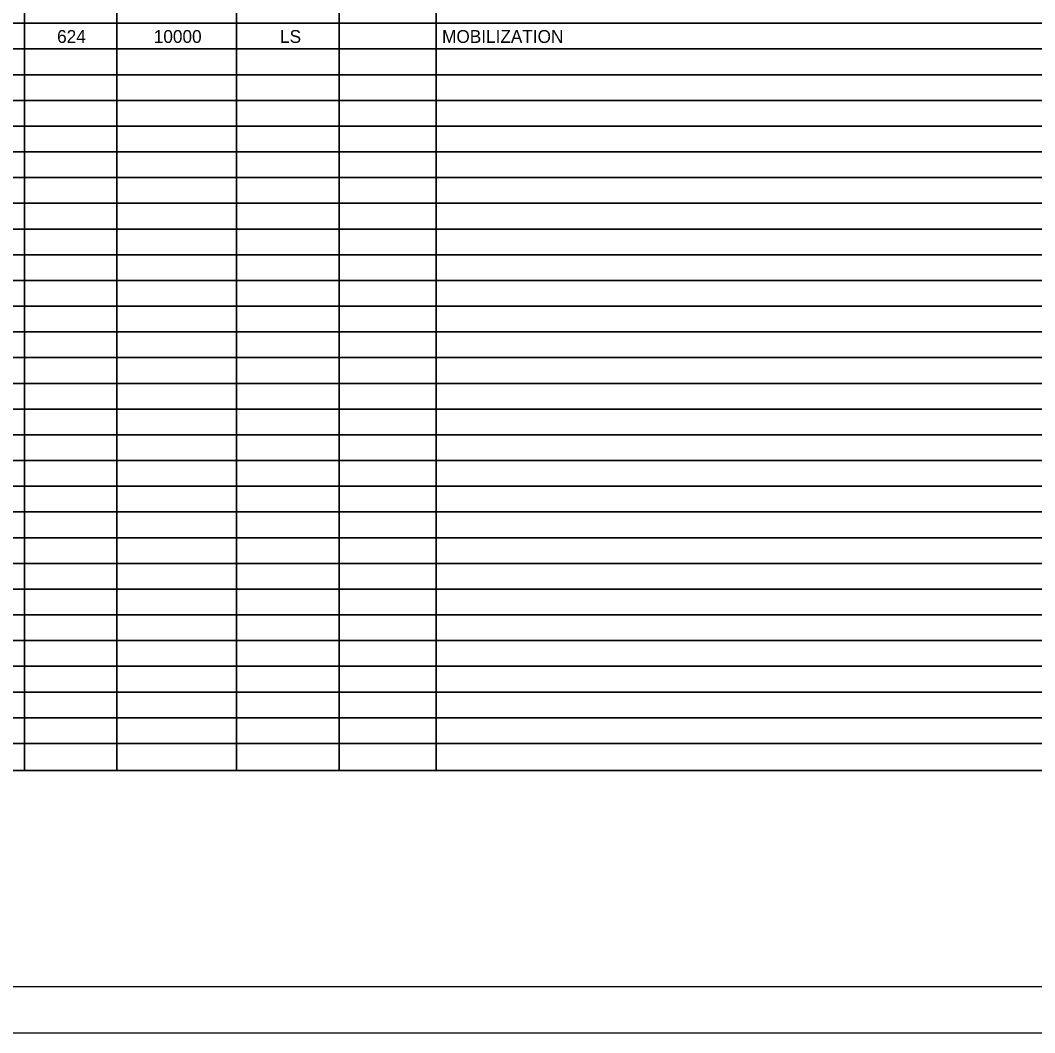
# Model space of a CAD drawing. Extents: x 0 to 34, y 0 to 22.
# Drawn here: x 11.97 to 23.01, y 0 to 11.02 of the extents above; entities that cross this region are included whole.
import ezdxf

# ---------------------------------------------------------------- set-up
doc = ezdxf.new("R2010")
doc.units = 0
for name, color, linetype in [('SH_Border', 7, 'Continuous'), ('SH_Cut_Line', 7, 'Continuous'), ('SH_Data', 7, 'Continuous'), ('SH_Text', 7, 'Continuous')]:
    doc.layers.add(name, color=color, linetype=linetype)

msp = doc.modelspace()

# ---------------------------------------------------------------- linework, layer by layer
at = {"layer": 'SH_Border'}
msp.add_lwpolyline([(1.5, 21.5), (33.5, 21.5), (33.5, 0.5), (1.5, 0.5)], close=True, dxfattribs=at)
at = {"layer": 'SH_Cut_Line'}
msp.add_lwpolyline([(0, 0), (34, 0), (34, 22), (0, 22)], close=True, dxfattribs=at)
at = {"layer": 'SH_Data'}
for p, q in [((16.492, 18.5), (16.492, 2.853)), ((12.012, 14.909), (12.012, 2.853)), ((13.016, 14.909), (13.016, 2.853)), ((14.318, 14.909), (14.318, 2.853)), ((15.438, 14.909), (15.438, 2.853)), ((6, 10.989), (27.049, 10.989)), ((6, 10.709), (27.049, 10.709)), ((6, 10.429), (27.049, 10.429)), ((6, 10.149), (27.049, 10.149)), ((6, 9.869), (27.049, 9.869)), ((6, 9.589), (27.049, 9.589)), ((6, 9.309), (27.049, 9.309)), ((6, 9.029), (27.049, 9.029)), ((6, 8.749), (27.049, 8.749)), ((6, 8.469), (27.049, 8.469)), ((6, 8.189), (27.049, 8.189)), ((6, 7.909), (27.049, 7.909)), ((6, 7.629), (27.049, 7.629)), ((6, 7.349), (27.049, 7.349)), ((6, 7.069), (27.049, 7.069)), ((6, 6.789), (27.049, 6.789)), ((6, 6.509), (27.049, 6.509)), ((6, 6.229), (27.049, 6.229)), ((6, 5.949), (27.049, 5.949)), ((6, 5.669), (27.049, 5.669)), ((6, 5.389), (27.049, 5.389)), ((6, 5.109), (27.049, 5.109)), ((6, 4.829), (27.049, 4.829)), ((6, 4.549), (27.049, 4.549)), ((6, 4.269), (27.049, 4.269)), ((6, 3.989), (27.049, 3.989)), ((6, 3.709), (27.049, 3.709)), ((6, 3.429), (27.049, 3.429)), ((6, 3.149), (27.049, 3.149)), ((6, 2.853), (27.049, 2.853))]:
    msp.add_line(p, q, dxfattribs=at)
at = {"layer": 'SH_Text'}
for points in [[(10.216, 11.269), (12.012, 11.269), (12.012, 10.989), (10.216, 10.989)], [(12.012, 11.269), (13.016, 11.269), (13.016, 10.989), (12.012, 10.989)], [(13.016, 11.269), (14.318, 11.269), (14.318, 10.989), (13.016, 10.989)], [(14.318, 11.269), (15.438, 11.269), (15.438, 10.989), (14.318, 10.989)], [(15.438, 11.269), (16.492, 11.269), (16.492, 10.989), (15.438, 10.989)], [(16.492, 11.269), (25.765, 11.269), (25.765, 10.989), (16.492, 10.989)], [(10.216, 10.989), (12.012, 10.989), (12.012, 10.709), (10.216, 10.709)], [(12.012, 10.989), (13.016, 10.989), (13.016, 10.709), (12.012, 10.709)], [(13.016, 10.989), (14.318, 10.989), (14.318, 10.709), (13.016, 10.709)], [(14.318, 10.989), (15.438, 10.989), (15.438, 10.709), (14.318, 10.709)], [(15.438, 10.989), (16.492, 10.989), (16.492, 10.709), (15.438, 10.709)], [(16.492, 10.989), (25.765, 10.989), (25.765, 10.709), (16.492, 10.709)], [(10.216, 10.709), (12.012, 10.709), (12.012, 10.429), (10.216, 10.429)], [(12.012, 10.709), (13.016, 10.709), (13.016, 10.429), (12.012, 10.429)], [(13.016, 10.709), (14.318, 10.709), (14.318, 10.429), (13.016, 10.429)], [(14.318, 10.709), (15.438, 10.709), (15.438, 10.429), (14.318, 10.429)], [(15.438, 10.709), (16.492, 10.709), (16.492, 10.429), (15.438, 10.429)], [(16.492, 10.709), (25.765, 10.709), (25.765, 10.429), (16.492, 10.429)], [(10.216, 10.429), (12.012, 10.429), (12.012, 10.149), (10.216, 10.149)], [(12.012, 10.429), (13.016, 10.429), (13.016, 10.149), (12.012, 10.149)], [(13.016, 10.429), (14.318, 10.429), (14.318, 10.149), (13.016, 10.149)], [(14.318, 10.429), (15.438, 10.429), (15.438, 10.149), (14.318, 10.149)], [(15.438, 10.429), (16.492, 10.429), (16.492, 10.149), (15.438, 10.149)], [(16.492, 10.429), (25.765, 10.429), (25.765, 10.149), (16.492, 10.149)], [(10.216, 10.149), (12.012, 10.149), (12.012, 9.869), (10.216, 9.869)], [(12.012, 10.149), (13.016, 10.149), (13.016, 9.869), (12.012, 9.869)], [(13.016, 10.149), (14.318, 10.149), (14.318, 9.869), (13.016, 9.869)], [(14.318, 10.149), (15.438, 10.149), (15.438, 9.869), (14.318, 9.869)], [(15.438, 10.149), (16.492, 10.149), (16.492, 9.869), (15.438, 9.869)], [(16.492, 10.149), (25.765, 10.149), (25.765, 9.869), (16.492, 9.869)], [(10.216, 9.869), (12.012, 9.869), (12.012, 9.589), (10.216, 9.589)], [(12.012, 9.869), (13.016, 9.869), (13.016, 9.589), (12.012, 9.589)], [(13.016, 9.869), (14.318, 9.869), (14.318, 9.589), (13.016, 9.589)], [(14.318, 9.869), (15.438, 9.869), (15.438, 9.589), (14.318, 9.589)], [(15.438, 9.869), (16.492, 9.869), (16.492, 9.589), (15.438, 9.589)], [(16.492, 9.869), (25.765, 9.869), (25.765, 9.589), (16.492, 9.589)], [(10.216, 9.589), (12.012, 9.589), (12.012, 9.309), (10.216, 9.309)], [(12.012, 9.589), (13.016, 9.589), (13.016, 9.309), (12.012, 9.309)], [(13.016, 9.589), (14.318, 9.589), (14.318, 9.309), (13.016, 9.309)], [(14.318, 9.589), (15.438, 9.589), (15.438, 9.309), (14.318, 9.309)], [(15.438, 9.589), (16.492, 9.589), (16.492, 9.309), (15.438, 9.309)], [(16.492, 9.589), (25.765, 9.589), (25.765, 9.309), (16.492, 9.309)], [(10.216, 9.309), (12.012, 9.309), (12.012, 9.029), (10.216, 9.029)], [(12.012, 9.309), (13.016, 9.309), (13.016, 9.029), (12.012, 9.029)], [(13.016, 9.309), (14.318, 9.309), (14.318, 9.029), (13.016, 9.029)], [(14.318, 9.309), (15.438, 9.309), (15.438, 9.029), (14.318, 9.029)], [(15.438, 9.309), (16.492, 9.309), (16.492, 9.029), (15.438, 9.029)], [(16.492, 9.309), (25.765, 9.309), (25.765, 9.029), (16.492, 9.029)], [(10.216, 9.029), (12.012, 9.029), (12.012, 8.749), (10.216, 8.749)], [(12.012, 9.029), (13.016, 9.029), (13.016, 8.749), (12.012, 8.749)], [(13.016, 9.029), (14.318, 9.029), (14.318, 8.749), (13.016, 8.749)], [(14.318, 9.029), (15.438, 9.029), (15.438, 8.749), (14.318, 8.749)], [(15.438, 9.029), (16.492, 9.029), (16.492, 8.749), (15.438, 8.749)], [(16.492, 9.029), (25.765, 9.029), (25.765, 8.749), (16.492, 8.749)], [(10.216, 8.749), (12.012, 8.749), (12.012, 8.469), (10.216, 8.469)], [(12.012, 8.749), (13.016, 8.749), (13.016, 8.469), (12.012, 8.469)], [(13.016, 8.749), (14.318, 8.749), (14.318, 8.469), (13.016, 8.469)], [(14.318, 8.749), (15.438, 8.749), (15.438, 8.469), (14.318, 8.469)], [(15.438, 8.749), (16.492, 8.749), (16.492, 8.469), (15.438, 8.469)], [(16.492, 8.749), (25.765, 8.749), (25.765, 8.469), (16.492, 8.469)], [(10.216, 8.469), (12.012, 8.469), (12.012, 8.189), (10.216, 8.189)], [(12.012, 8.469), (13.016, 8.469), (13.016, 8.189), (12.012, 8.189)], [(13.016, 8.469), (14.318, 8.469), (14.318, 8.189), (13.016, 8.189)], [(14.318, 8.469), (15.438, 8.469), (15.438, 8.189), (14.318, 8.189)], [(15.438, 8.469), (16.492, 8.469), (16.492, 8.189), (15.438, 8.189)], [(16.492, 8.469), (25.765, 8.469), (25.765, 8.189), (16.492, 8.189)], [(10.216, 8.189), (12.012, 8.189), (12.012, 7.909), (10.216, 7.909)], [(12.012, 8.189), (13.016, 8.189), (13.016, 7.909), (12.012, 7.909)], [(13.016, 8.189), (14.318, 8.189), (14.318, 7.909), (13.016, 7.909)], [(14.318, 8.189), (15.438, 8.189), (15.438, 7.909), (14.318, 7.909)], [(15.438, 8.189), (16.492, 8.189), (16.492, 7.909), (15.438, 7.909)], [(16.492, 8.189), (25.765, 8.189), (25.765, 7.909), (16.492, 7.909)], [(10.216, 7.909), (12.012, 7.909), (12.012, 7.629), (10.216, 7.629)], [(12.012, 7.909), (13.016, 7.909), (13.016, 7.629), (12.012, 7.629)], [(13.016, 7.909), (14.318, 7.909), (14.318, 7.629), (13.016, 7.629)], [(14.318, 7.909), (15.438, 7.909), (15.438, 7.629), (14.318, 7.629)], [(15.438, 7.909), (16.492, 7.909), (16.492, 7.629), (15.438, 7.629)], [(16.492, 7.909), (25.765, 7.909), (25.765, 7.629), (16.492, 7.629)], [(10.216, 7.629), (12.012, 7.629), (12.012, 7.349), (10.216, 7.349)], [(12.012, 7.629), (13.016, 7.629), (13.016, 7.349), (12.012, 7.349)], [(13.016, 7.629), (14.318, 7.629), (14.318, 7.349), (13.016, 7.349)], [(14.318, 7.629), (15.438, 7.629), (15.438, 7.349), (14.318, 7.349)], [(15.438, 7.629), (16.492, 7.629), (16.492, 7.349), (15.438, 7.349)], [(16.492, 7.629), (25.765, 7.629), (25.765, 7.349), (16.492, 7.349)], [(10.216, 7.349), (12.012, 7.349), (12.012, 7.069), (10.216, 7.069)], [(12.012, 7.349), (13.016, 7.349), (13.016, 7.069), (12.012, 7.069)], [(13.016, 7.349), (14.318, 7.349), (14.318, 7.069), (13.016, 7.069)], [(14.318, 7.349), (15.438, 7.349), (15.438, 7.069), (14.318, 7.069)], [(15.438, 7.349), (16.492, 7.349), (16.492, 7.069), (15.438, 7.069)], [(16.492, 7.349), (25.765, 7.349), (25.765, 7.069), (16.492, 7.069)], [(10.216, 7.069), (12.012, 7.069), (12.012, 6.789), (10.216, 6.789)], [(12.012, 7.069), (13.016, 7.069), (13.016, 6.789), (12.012, 6.789)], [(13.016, 7.069), (14.318, 7.069), (14.318, 6.789), (13.016, 6.789)], [(14.318, 7.069), (15.438, 7.069), (15.438, 6.789), (14.318, 6.789)], [(15.438, 7.069), (16.492, 7.069), (16.492, 6.789), (15.438, 6.789)], [(16.492, 7.069), (25.765, 7.069), (25.765, 6.789), (16.492, 6.789)], [(10.216, 6.789), (12.012, 6.789), (12.012, 6.509), (10.216, 6.509)], [(12.012, 6.789), (13.016, 6.789), (13.016, 6.509), (12.012, 6.509)], [(13.016, 6.789), (14.318, 6.789), (14.318, 6.509), (13.016, 6.509)], [(14.318, 6.789), (15.438, 6.789), (15.438, 6.509), (14.318, 6.509)], [(15.438, 6.789), (16.492, 6.789), (16.492, 6.509), (15.438, 6.509)], [(16.492, 6.789), (25.765, 6.789), (25.765, 6.509), (16.492, 6.509)], [(10.216, 6.509), (12.012, 6.509), (12.012, 6.229), (10.216, 6.229)], [(12.012, 6.509), (13.016, 6.509), (13.016, 6.229), (12.012, 6.229)], [(13.016, 6.509), (14.318, 6.509), (14.318, 6.229), (13.016, 6.229)], [(14.318, 6.509), (15.438, 6.509), (15.438, 6.229), (14.318, 6.229)], [(15.438, 6.509), (16.492, 6.509), (16.492, 6.229), (15.438, 6.229)], [(16.492, 6.509), (25.765, 6.509), (25.765, 6.229), (16.492, 6.229)], [(10.216, 6.229), (12.012, 6.229), (12.012, 5.949), (10.216, 5.949)], [(12.012, 6.229), (13.016, 6.229), (13.016, 5.949), (12.012, 5.949)], [(13.016, 6.229), (14.318, 6.229), (14.318, 5.949), (13.016, 5.949)], [(14.318, 6.229), (15.438, 6.229), (15.438, 5.949), (14.318, 5.949)], [(15.438, 6.229), (16.492, 6.229), (16.492, 5.949), (15.438, 5.949)], [(16.492, 6.229), (25.765, 6.229), (25.765, 5.949), (16.492, 5.949)], [(10.216, 5.949), (12.012, 5.949), (12.012, 5.669), (10.216, 5.669)], [(12.012, 5.949), (13.016, 5.949), (13.016, 5.669), (12.012, 5.669)], [(13.016, 5.949), (14.318, 5.949), (14.318, 5.669), (13.016, 5.669)], [(14.318, 5.949), (15.438, 5.949), (15.438, 5.669), (14.318, 5.669)], [(15.438, 5.949), (16.492, 5.949), (16.492, 5.669), (15.438, 5.669)], [(16.492, 5.949), (25.765, 5.949), (25.765, 5.669), (16.492, 5.669)], [(10.216, 5.669), (12.012, 5.669), (12.012, 5.389), (10.216, 5.389)], [(12.012, 5.669), (13.016, 5.669), (13.016, 5.389), (12.012, 5.389)], [(13.016, 5.669), (14.318, 5.669), (14.318, 5.389), (13.016, 5.389)], [(14.318, 5.669), (15.438, 5.669), (15.438, 5.389), (14.318, 5.389)], [(15.438, 5.669), (16.492, 5.669), (16.492, 5.389), (15.438, 5.389)], [(16.492, 5.669), (25.765, 5.669), (25.765, 5.389), (16.492, 5.389)], [(10.216, 5.389), (12.012, 5.389), (12.012, 5.109), (10.216, 5.109)], [(12.012, 5.389), (13.016, 5.389), (13.016, 5.109), (12.012, 5.109)], [(13.016, 5.389), (14.318, 5.389), (14.318, 5.109), (13.016, 5.109)], [(14.318, 5.389), (15.438, 5.389), (15.438, 5.109), (14.318, 5.109)], [(15.438, 5.389), (16.492, 5.389), (16.492, 5.109), (15.438, 5.109)], [(16.492, 5.389), (25.765, 5.389), (25.765, 5.109), (16.492, 5.109)], [(10.216, 5.109), (12.012, 5.109), (12.012, 4.829), (10.216, 4.829)], [(12.012, 5.109), (13.016, 5.109), (13.016, 4.829), (12.012, 4.829)], [(13.016, 5.109), (14.318, 5.109), (14.318, 4.829), (13.016, 4.829)], [(14.318, 5.109), (15.438, 5.109), (15.438, 4.829), (14.318, 4.829)], [(15.438, 5.109), (16.492, 5.109), (16.492, 4.829), (15.438, 4.829)], [(16.492, 5.109), (25.765, 5.109), (25.765, 4.829), (16.492, 4.829)], [(10.216, 4.829), (12.012, 4.829), (12.012, 4.549), (10.216, 4.549)], [(12.012, 4.829), (13.016, 4.829), (13.016, 4.549), (12.012, 4.549)], [(13.016, 4.829), (14.318, 4.829), (14.318, 4.549), (13.016, 4.549)], [(14.318, 4.829), (15.438, 4.829), (15.438, 4.549), (14.318, 4.549)], [(15.438, 4.829), (16.492, 4.829), (16.492, 4.549), (15.438, 4.549)], [(16.492, 4.829), (25.765, 4.829), (25.765, 4.549), (16.492, 4.549)], [(10.216, 4.549), (12.012, 4.549), (12.012, 4.269), (10.216, 4.269)], [(12.012, 4.549), (13.016, 4.549), (13.016, 4.269), (12.012, 4.269)], [(13.016, 4.549), (14.318, 4.549), (14.318, 4.269), (13.016, 4.269)], [(14.318, 4.549), (15.438, 4.549), (15.438, 4.269), (14.318, 4.269)], [(15.438, 4.549), (16.492, 4.549), (16.492, 4.269), (15.438, 4.269)], [(16.492, 4.549), (25.765, 4.549), (25.765, 4.269), (16.492, 4.269)], [(10.216, 4.269), (12.012, 4.269), (12.012, 3.989), (10.216, 3.989)], [(12.012, 4.269), (13.016, 4.269), (13.016, 3.989), (12.012, 3.989)], [(13.016, 4.269), (14.318, 4.269), (14.318, 3.989), (13.016, 3.989)], [(14.318, 4.269), (15.438, 4.269), (15.438, 3.989), (14.318, 3.989)], [(15.438, 4.269), (16.492, 4.269), (16.492, 3.989), (15.438, 3.989)], [(16.492, 4.269), (25.765, 4.269), (25.765, 3.989), (16.492, 3.989)], [(10.216, 3.989), (12.012, 3.989), (12.012, 3.709), (10.216, 3.709)], [(12.012, 3.989), (13.016, 3.989), (13.016, 3.709), (12.012, 3.709)], [(13.016, 3.989), (14.318, 3.989), (14.318, 3.709), (13.016, 3.709)], [(14.318, 3.989), (15.438, 3.989), (15.438, 3.709), (14.318, 3.709)], [(15.438, 3.989), (16.492, 3.989), (16.492, 3.709), (15.438, 3.709)], [(16.492, 3.989), (25.765, 3.989), (25.765, 3.709), (16.492, 3.709)], [(10.216, 3.709), (12.012, 3.709), (12.012, 3.429), (10.216, 3.429)], [(12.012, 3.709), (13.016, 3.709), (13.016, 3.429), (12.012, 3.429)], [(13.016, 3.709), (14.318, 3.709), (14.318, 3.429), (13.016, 3.429)], [(14.318, 3.709), (15.438, 3.709), (15.438, 3.429), (14.318, 3.429)], [(15.438, 3.709), (16.492, 3.709), (16.492, 3.429), (15.438, 3.429)], [(16.492, 3.709), (25.765, 3.709), (25.765, 3.429), (16.492, 3.429)], [(10.216, 3.429), (12.012, 3.429), (12.012, 3.149), (10.216, 3.149)], [(12.012, 3.429), (13.016, 3.429), (13.016, 3.149), (12.012, 3.149)], [(13.016, 3.429), (14.318, 3.429), (14.318, 3.149), (13.016, 3.149)], [(14.318, 3.429), (15.438, 3.429), (15.438, 3.149), (14.318, 3.149)], [(15.438, 3.429), (16.492, 3.429), (16.492, 3.149), (15.438, 3.149)], [(16.492, 3.429), (25.765, 3.429), (25.765, 3.149), (16.492, 3.149)], [(10.216, 3.149), (12.012, 3.149), (12.012, 2.853), (10.216, 2.853)], [(12.012, 3.149), (13.016, 3.149), (13.016, 2.853), (12.012, 2.853)], [(13.016, 3.149), (14.318, 3.149), (14.318, 2.853), (13.016, 2.853)], [(14.318, 3.149), (15.438, 3.149), (15.438, 2.853), (14.318, 2.853)], [(15.438, 3.149), (16.492, 3.149), (16.492, 2.853), (15.438, 2.853)], [(16.492, 3.149), (25.765, 3.149), (25.765, 2.853), (16.492, 2.853)]]:
    msp.add_lwpolyline(points, close=True, dxfattribs=at)

# ---------------------------------------------------------------- texts
for s, p in [('624', (12.366, 10.775)), ('10000', (13.419, 10.775)), ('LS', (14.794, 10.775)), ('MOBILIZATION', (16.558, 10.775))]:
    msp.add_text(s, height=0.14, dxfattribs=at).set_placement(p)

doc.saveas('drawing.dxf')
